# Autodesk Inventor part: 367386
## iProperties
Created: 2006-07
Part Number: 367386
Material: A2
Description: Senkschraube
Vendor: Autodesk Inc.
Document SubType Name: Modeling
Standard: DIN 7991
Designer: I.Baliuc
Standards Organization: DIN
Language: de-DE
Size Designation: M10 x 40
Categories: <MemberInstance Version="R10.0.0"><Categories><Category DisplayName="Schrauben" InternalName="e4da775c-781d-43d5-af7c-5136215cf5a6" Mnemonic="FSTN"><Category Di
Density: 8.08 g/cm^3
Abmessung: M10 x 40
Author: T.Messerschmitt
Comments: DIN 7991 - M10 x 40
Revision Number: 367386
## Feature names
1. Körper [Revolution]
2. Loch [Extrusion]
3. Fase1 [Chamfer]
